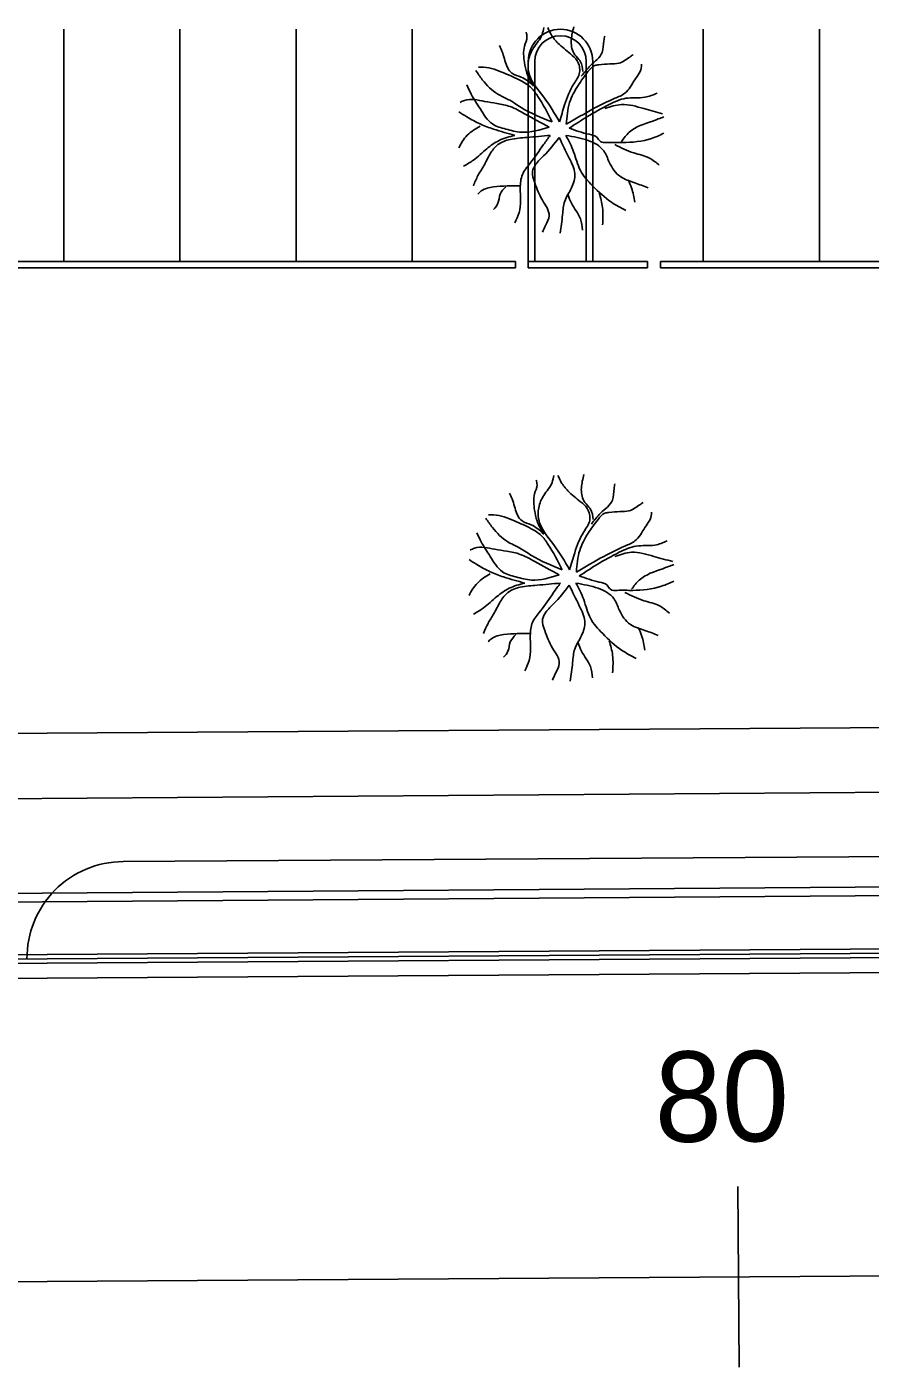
# Model space of a CAD drawing. Extents: x 6711323 to 6714641, y 1869258 to 1871224.
# Drawn here: x 6712796.7 to 6712862, y 1869583.4 to 1869687.3 of the extents above; entities that cross this region are included whole.
import ezdxf

# ---------------------------------------------------------------- set-up
doc = ezdxf.new("R2010")
doc.units = 0
for name, color, linetype in [('Curb Gutter (21)', 7, 'Continuous'), ('Front Align (17)', 7, 'Continuous'), ('Level 11', 7, 'Continuous'), ('Level 13', 7, 'Continuous'), ('Level 14', 7, 'Continuous'), ('Level 21', 7, 'Continuous'), ('Level 46', 7, 'Continuous'), ('Profile Grid (9)', 7, 'Continuous'), ('Undefined (Lv19)', 7, 'Continuous')]:
    doc.layers.add(name, color=color, linetype=linetype)

msp = doc.modelspace()

# ---------------------------------------------------------------- linework, layer by layer
at = {"layer": 'Curb Gutter (21)'}
for p, q in [((6712835.54, 1869684.57), (6712835.54, 1869669.07)), ((6712836.04, 1869684.57), (6712836.04, 1869669.07)), ((6712840.04, 1869684.57), (6712840.04, 1869669.07)), ((6712840.54, 1869684.57), (6712840.54, 1869669.07)), ((6712781.54, 1869669.07), (6712834.54, 1869669.07)), ((6712835.54, 1869669.07), (6712840.67, 1869669.07)), ((6712844.79, 1869669.07), (6712840.54, 1869669.07)), ((6712894.11, 1869669.07), (6712845.79, 1869669.07)), ((6712776.54, 1869668.57), (6712834.54, 1869668.57)), ((6712835.54, 1869668.57), (6712841.37, 1869668.57)), ((6712844.79, 1869668.57), (6712840.54, 1869668.57)), ((6712894.61, 1869668.57), (6712845.79, 1869668.57))]:
    msp.add_line(p, q, dxfattribs=at)
for radius in [2.5, 2]:
    msp.add_arc((6712838.04, 1869684.57), radius, 360, 180, dxfattribs=at)
at = {"layer": 'Front Align (17)'}
for p, q in [((6712799.54, 1869669.07), (6712799.54, 1869687.07)), ((6712808.54, 1869669.07), (6712808.54, 1869687.07)), ((6712817.54, 1869669.07), (6712817.54, 1869687.07)), ((6712826.54, 1869669.07), (6712826.54, 1869687.07)), ((6712849.11, 1869669.07), (6712849.11, 1869687.07)), ((6712858.11, 1869669.07), (6712858.11, 1869687.07))]:
    msp.add_line(p, q, dxfattribs=at)
at = {"layer": 'Level 11'}
for p, q in [((6712708.78, 1869631.94), (6712900.92, 1869633.18)), ((6712804.13, 1869622.56), (6712900.98, 1869623.18)), ((6712708.9, 1869614.44), (6712891.02, 1869615.62)), ((6712708.91, 1869612.94), (6712948.69, 1869614.49))]:
    msp.add_line(p, q, dxfattribs=at)
msp.add_arc((6712804.18, 1869615.06), 7.5, 90.3699, 180.3699, dxfattribs=at)
at = {"layer": 'Level 13'}
msp.add_line((6712709.06, 1869589.44), (6713820.2, 1869596.61), dxfattribs=at)
msp.add_arc((6712804.18, 1869615.06), 7.5, 90.3699, 180.3699, dxfattribs=at)
at = {"layer": 'Level 14'}
msp.add_lwpolyline([(6712851.79, 1869597.36), (6712851.88, 1869583.36)], dxfattribs=at)
at = {"layer": 'Level 21'}
for p, q in [((6712708.78, 1869631.94), (6712899.57, 1869633.17)), ((6712804.13, 1869622.56), (6712899.63, 1869623.17)), ((6712708.9, 1869614.44), (6712891.02, 1869615.62)), ((6712708.91, 1869612.94), (6712948.69, 1869614.49))]:
    msp.add_line(p, q, dxfattribs=at)
at = {"layer": 'Level 46'}
for p, q in [((6712708.93, 1869626.81), (6712900.18, 1869628.18)), ((6712708.99, 1869619.48), (6712895.93, 1869620.81)), ((6712708.99, 1869618.81), (6712895.26, 1869620.14)), ((6712709.32, 1869614.79), (6712887.86, 1869615.93)), ((6712709.32, 1869614.12), (6712883.01, 1869615.23))]:
    msp.add_line(p, q, dxfattribs=at)
at = {"layer": 'Profile Grid (9)'}
for points in [[(6712835.96, 1869682.65), (6712835.44, 1869683.67), (6712835.25, 1869684.5), (6712835.25, 1869685.76), (6712835.44, 1869686.48), (6712835.38, 1869686.84)], [(6712837.97, 1869679.89), (6712836.74, 1869681.81), (6712835.57, 1869683.79), (6712835.57, 1869684.68), (6712835.96, 1869685.64), (6712836.61, 1869686.66), (6712836.74, 1869687.2)], [(6712837.97, 1869679.89), (6712838.36, 1869681.21), (6712839.07, 1869682.83), (6712839.52, 1869683.73), (6712839.33, 1869684.62), (6712838.81, 1869685.16), (6712837.84, 1869686), (6712837.32, 1869686.66), (6712837.06, 1869687.2)], [(6712839.78, 1869683.79), (6712839.59, 1869684.56), (6712839.46, 1869684.74), (6712839.07, 1869685.22), (6712838.88, 1869686.24), (6712839.07, 1869687.26)], [(6712839.65, 1869683.43), (6712840.37, 1869684.26), (6712841.27, 1869685.28), (6712841.4, 1869686.18), (6712841.47, 1869686.54)], [(6712835.96, 1869682.65), (6712834.99, 1869683.37), (6712834.28, 1869683.67), (6712833.95, 1869684.08), (6712833.56, 1869685.22), (6712833.3, 1869685.82)], [(6712838.49, 1869679.71), (6712838.75, 1869681.39), (6712839.4, 1869682.71), (6712840.17, 1869683.79), (6712840.69, 1869684.26), (6712841.02, 1869684.32), (6712841.86, 1869684.38), (6712842.57, 1869684.44), (6712843.41, 1869684.92), (6712843.67, 1869685.1)], [(6712838.49, 1869679.71), (6712840.61, 1869680.92), (6712842.25, 1869681.72), (6712843.03, 1869682.12), (6712843.8, 1869683.16), (6712844.32, 1869684.2), (6712844.32, 1869684.36)], [(6712837.39, 1869679.89), (6712835, 1869681), (6712833.97, 1869681.64), (6712833.19, 1869682.04), (6712831.98, 1869683.16), (6712831.47, 1869683.88)], [(6712837.39, 1869679.89), (6712836.29, 1869681.87), (6712835.77, 1869682.53), (6712834.99, 1869683.07), (6712833.69, 1869683.67), (6712832.07, 1869684.14), (6712831.68, 1869684.14)], [(6712837.16, 1869679.49), (6712835, 1869679.09), (6712833.8, 1869679.33), (6712832.76, 1869679.73), (6712831.81, 1869680.92), (6712831.12, 1869682.04), (6712830.78, 1869682.76)], [(6712837.16, 1869679.49), (6712835.26, 1869680.52), (6712834.14, 1869681.08), (6712833.11, 1869681.32), (6712832.16, 1869681.48), (6712830.6, 1869681.56), (6712830.26, 1869681.4)], [(6712838.71, 1869679.41), (6712840.09, 1869680.28), (6712841.82, 1869681.24), (6712843.11, 1869681.72), (6712844.58, 1869681.8), (6712845.53, 1869682.12)], [(6712841.48, 1869680.92), (6712842.77, 1869681.24), (6712844.5, 1869680.92), (6712845.96, 1869680.52)], [(6712834.49, 1869678.85), (6712832.85, 1869679.33), (6712831.81, 1869679.73), (6712830.78, 1869680.28), (6712830.17, 1869680.68)], [(6712842.77, 1869678.37), (6712843.37, 1869679.09), (6712845.19, 1869679.96), (6712846.05, 1869680.28)], [(6712831.81, 1869679.57), (6712831.29, 1869679.25), (6712830.43, 1869678.37), (6712830.17, 1869677.89)], [(6712838.71, 1869679.41), (6712840.27, 1869678.93), (6712840.87, 1869678.69), (6712841.13, 1869678.37), (6712841.65, 1869678.29), (6712842.86, 1869678.29), (6712845.1, 1869678.61), (6712846.05, 1869679.01)], [(6712834.49, 1869678.85), (6712833.28, 1869678.45), (6712832.33, 1869677.81), (6712831.29, 1869676.93), (6712830.52, 1869676.45)], [(6712837.25, 1869678.85), (6712835.44, 1869678.69), (6712834.14, 1869678.53), (6712833.19, 1869678.13), (6712832.59, 1869677.41), (6712832.07, 1869676.45), (6712831.64, 1869675.73), (6712831.29, 1869674.93)], [(6712837.25, 1869678.85), (6712836.73, 1869678.13), (6712835.69, 1869676.69), (6712835.09, 1869675.81), (6712834.92, 1869674.77), (6712834.83, 1869672.86), (6712834.49, 1869672.06)], [(6712837.94, 1869678.69), (6712836.73, 1869677.25), (6712836.13, 1869676.61), (6712835.87, 1869676.05), (6712836.04, 1869675.17), (6712836.64, 1869673.82), (6712837.16, 1869672.62), (6712836.9, 1869671.9), (6712836.64, 1869671.34)], [(6712837.94, 1869678.69), (6712838.71, 1869677.09), (6712839.15, 1869675.89), (6712838.89, 1869674.77), (6712838.37, 1869673.74), (6712838.2, 1869672.7), (6712838.02, 1869671.26)], [(6712838.46, 1869678.85), (6712839.06, 1869677.57), (6712839.58, 1869676.13), (6712840.53, 1869674.93), (6712841.99, 1869673.66), (6712843.11, 1869673.02)], [(6712838.46, 1869678.85), (6712840.18, 1869678.45), (6712840.87, 1869678.13), (6712841.39, 1869677.65), (6712841.82, 1869676.77), (6712842.68, 1869675.65), (6712843.8, 1869675.17), (6712844.84, 1869674.77)], [(6712842.25, 1869678.13), (6712843.72, 1869677.49), (6712844.93, 1869677.09), (6712845.7, 1869676.53)], [(6712834.92, 1869674.93), (6712832.85, 1869674.85), (6712831.9, 1869674.54), (6712831.64, 1869674.3)], [(6712843.29, 1869675.41), (6712843.55, 1869674.77), (6712843.8, 1869673.66)], [(6712833.8, 1869674.85), (6712833.36, 1869674.3), (6712833.19, 1869673.58), (6712832.85, 1869673.1)], [(6712838.63, 1869674.22), (6712838.89, 1869673.58), (6712839.58, 1869672.38), (6712839.75, 1869671.5)], [(6712841.04, 1869674.38), (6712841.3, 1869673.26), (6712841.3, 1869671.9)], [(6712836.74, 1869647.94), (6712836.22, 1869648.96), (6712836.03, 1869649.8), (6712836.03, 1869651.05), (6712836.22, 1869651.77), (6712836.16, 1869652.13)], [(6712838.75, 1869645.18), (6712837.52, 1869647.1), (6712836.35, 1869649.08), (6712836.35, 1869649.98), (6712836.74, 1869650.93), (6712837.39, 1869651.95), (6712837.52, 1869652.49)], [(6712838.75, 1869645.18), (6712839.14, 1869646.5), (6712839.85, 1869648.12), (6712840.31, 1869649.02), (6712840.11, 1869649.92), (6712839.59, 1869650.45), (6712838.62, 1869651.29), (6712838.1, 1869651.95), (6712837.84, 1869652.49)], [(6712840.57, 1869649.08), (6712840.37, 1869649.86), (6712840.24, 1869650.04), (6712839.85, 1869650.52), (6712839.66, 1869651.53), (6712839.85, 1869652.55)], [(6712836.74, 1869647.94), (6712835.77, 1869648.66), (6712835.06, 1869648.96), (6712834.73, 1869649.38), (6712834.34, 1869650.52), (6712834.09, 1869651.11)], [(6712840.44, 1869648.72), (6712841.15, 1869649.56), (6712842.06, 1869650.57), (6712842.19, 1869651.47), (6712842.25, 1869651.83)], [(6712839.27, 1869645), (6712839.53, 1869646.68), (6712840.18, 1869648), (6712840.95, 1869649.08), (6712841.47, 1869649.56), (6712841.8, 1869649.62), (6712842.64, 1869649.68), (6712843.35, 1869649.74), (6712844.19, 1869650.22), (6712844.45, 1869650.4)], [(6712838.17, 1869645.18), (6712835.79, 1869646.29), (6712834.75, 1869646.93), (6712833.97, 1869647.33), (6712832.77, 1869648.45), (6712832.25, 1869649.17)], [(6712838.17, 1869645.18), (6712837.07, 1869647.16), (6712836.55, 1869647.82), (6712835.77, 1869648.36), (6712834.47, 1869648.96), (6712832.85, 1869649.44), (6712832.47, 1869649.44)], [(6712839.27, 1869645), (6712841.39, 1869646.21), (6712843.03, 1869647.01), (6712843.81, 1869647.41), (6712844.59, 1869648.45), (6712845.1, 1869649.49), (6712845.1, 1869649.65)], [(6712837.94, 1869644.78), (6712835.79, 1869644.38), (6712834.58, 1869644.62), (6712833.54, 1869645.02), (6712832.59, 1869646.21), (6712831.9, 1869647.33), (6712831.56, 1869648.05)], [(6712837.94, 1869644.78), (6712836.04, 1869645.81), (6712834.92, 1869646.37), (6712833.89, 1869646.61), (6712832.94, 1869646.77), (6712831.38, 1869646.85), (6712831.04, 1869646.69)], [(6712839.5, 1869644.7), (6712840.88, 1869645.58), (6712842.6, 1869646.53), (6712843.9, 1869647.01), (6712845.36, 1869647.09), (6712846.31, 1869647.41)], [(6712835.27, 1869644.14), (6712833.63, 1869644.62), (6712832.59, 1869645.02), (6712831.56, 1869645.58), (6712830.95, 1869645.97)], [(6712842.26, 1869646.21), (6712843.55, 1869646.53), (6712845.28, 1869646.21), (6712846.74, 1869645.81)], [(6712832.59, 1869644.86), (6712832.07, 1869644.54), (6712831.21, 1869643.66), (6712830.95, 1869643.18)], [(6712843.55, 1869643.66), (6712844.15, 1869644.38), (6712845.97, 1869645.26), (6712846.83, 1869645.58)], [(6712835.27, 1869644.14), (6712834.06, 1869643.74), (6712833.11, 1869643.1), (6712832.07, 1869642.22), (6712831.3, 1869641.74)], [(6712838.03, 1869644.14), (6712836.22, 1869643.98), (6712834.92, 1869643.82), (6712833.97, 1869643.42), (6712833.37, 1869642.7), (6712832.85, 1869641.74), (6712832.42, 1869641.02), (6712832.07, 1869640.23)], [(6712838.03, 1869644.14), (6712837.51, 1869643.42), (6712836.48, 1869641.98), (6712835.87, 1869641.1), (6712835.7, 1869640.07), (6712835.61, 1869638.15), (6712835.27, 1869637.35)], [(6712838.72, 1869643.98), (6712837.51, 1869642.54), (6712836.91, 1869641.9), (6712836.65, 1869641.34), (6712836.82, 1869640.47), (6712837.42, 1869639.11), (6712837.94, 1869637.91), (6712837.68, 1869637.19), (6712837.42, 1869636.63)], [(6712838.72, 1869643.98), (6712839.5, 1869642.38), (6712839.93, 1869641.18), (6712839.67, 1869640.07), (6712839.15, 1869639.03), (6712838.98, 1869637.99), (6712838.8, 1869636.55)], [(6712839.24, 1869644.14), (6712839.84, 1869642.86), (6712840.36, 1869641.42), (6712841.31, 1869640.23), (6712842.77, 1869638.95), (6712843.9, 1869638.31)], [(6712839.24, 1869644.14), (6712840.96, 1869643.74), (6712841.65, 1869643.42), (6712842.17, 1869642.94), (6712842.6, 1869642.06), (6712843.46, 1869640.94), (6712844.59, 1869640.47), (6712845.62, 1869640.07)], [(6712839.5, 1869644.7), (6712841.05, 1869644.22), (6712841.65, 1869643.98), (6712841.91, 1869643.66), (6712842.43, 1869643.58), (6712843.64, 1869643.58), (6712845.88, 1869643.9), (6712846.83, 1869644.3)], [(6712843.03, 1869643.42), (6712844.5, 1869642.78), (6712845.71, 1869642.38), (6712846.48, 1869641.82)], [(6712844.07, 1869640.7), (6712844.33, 1869640.07), (6712844.59, 1869638.95)], [(6712835.7, 1869640.23), (6712833.63, 1869640.15), (6712832.68, 1869639.83), (6712832.42, 1869639.59)], [(6712834.58, 1869640.15), (6712834.15, 1869639.59), (6712833.97, 1869638.87), (6712833.63, 1869638.39)], [(6712841.82, 1869639.67), (6712842.08, 1869638.55), (6712842.08, 1869637.19)], [(6712839.41, 1869639.51), (6712839.67, 1869638.87), (6712840.36, 1869637.67), (6712840.53, 1869636.79)]]:
    msp.add_spline(points, degree=3, dxfattribs=at)
at = {"layer": 'Undefined (Lv19)'}
for p, q in [((6712835.54, 1869669.07), (6712835.54, 1869675.55)), ((6712834.54, 1869669.07), (6712834.54, 1869668.57)), ((6712835.54, 1869669.07), (6712835.54, 1869668.57)), ((6712844.79, 1869669.07), (6712844.79, 1869668.57)), ((6712845.79, 1869669.07), (6712845.79, 1869668.57))]:
    msp.add_line(p, q, dxfattribs=at)

# ---------------------------------------------------------------- texts
at = {"layer": 'Level 14'}
msp.add_text('80', height=7, rotation=0.3699, dxfattribs=at).set_placement((6712845.36, 1869600.82))

doc.saveas('drawing.dxf')
